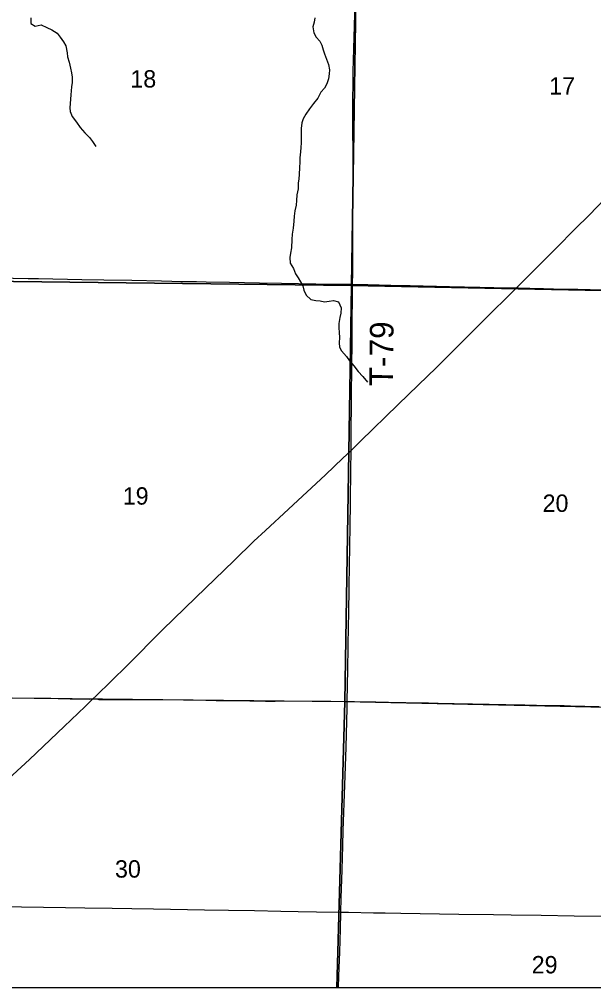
# Model space of a CAD drawing. Extents: x -8.5 to 18.7, y -20.3 to 7.
# Drawn here: x 11.753 to 14.521, y -20.262 to -15.596 of the extents above; entities that cross this region are included whole.
import ezdxf

# ---------------------------------------------------------------- set-up
doc = ezdxf.new("R2010")
doc.units = 0
for name, color, linetype in [('GM_X_Corporation', 7, 'Continuous'), ('GM_X_County_Road', 7, 'Continuous'), ('GM_X_Minor_River', 7, 'Continuous'), ('GM_X_Section', 7, 'Continuous'), ('GM_X_Section_Text', 7, 'Continuous'), ('GM_X_State_Route', 7, 'Continuous'), ('GM_X_Township_Road', 7, 'Continuous'), ('GM_X_Township_Road_Text', 7, 'Continuous'), ('GM_X_Unincorporated_Text', 7, 'Continuous'), ('SH_Cut_Line', 7, 'Continuous')]:
    doc.layers.add(name, color=color, linetype=linetype)

msp = doc.modelspace()

# ---------------------------------------------------------------- linework, layer by layer
at = {"layer": 'GM_X_Corporation'}
msp.add_lwpolyline([(11.351, -15.4961), (11.3472, -15.7708), (11.3457, -15.8603), (11.343, -16.0108), (11.3417, -16.0903), (11.339, -16.2358), (11.3374, -16.324), (11.3361, -16.4073), (11.3309, -16.7927), (11.331, -16.8266), (11.3313, -16.8312), (11.3321, -16.8414), (11.2969, -18.8581), (11.277, -19.7245), (11.2736, -19.8636), (11.2623, -20.262), (18.7413, -20.262)], dxfattribs=at)
at = {"layer": 'GM_X_County_Road'}
for points in [[(11.3326, -16.8425), (11.3671, -16.8392), (11.392, -16.8377), (11.4257, -16.8371), (11.4804, -16.8379), (11.5413, -16.8394), (11.6494, -16.841), (11.7961, -16.8438), (11.8446, -16.8445), (12.0534, -16.8489), (12.1603, -16.8513), (12.2958, -16.8534), (12.4375, -16.8563), (12.4873, -16.8575), (12.532, -16.8584), (12.6066, -16.8592), (12.6538, -16.8603), (12.7657, -16.8621), (12.9099, -16.8649), (13.0167, -16.8667), (13.1821, -16.8697), (13.2828, -16.8711), (13.3593, -16.8726)], [(13.3593, -16.8726), (13.4332, -16.8741), (13.5438, -16.8772), (13.637, -16.8789), (13.826, -16.8829), (13.9726, -16.8863), (14.0398, -16.8873), (14.1218, -16.8891), (14.1487, -16.8895)], [(14.1487, -16.8895), (14.1591, -16.8897), (14.2125, -16.8915), (14.2784, -16.893), (14.3268, -16.8937), (14.4449, -16.8962), (14.5643, -16.8985), (14.6686, -16.9014), (14.8228, -16.9045), (14.9657, -16.9071), (15.2454, -16.9126), (15.3212, -16.9133), (15.3705, -16.9142)], [(13.3333, -18.8824), (13.3362, -18.7269), (13.3397, -18.5155), (13.3406, -18.4646), (13.3433, -18.3266), (13.3467, -18.0382), (13.3487, -17.9276), (13.3513, -17.7572), (13.3517, -17.686), (13.3521, -17.673)], [(13.3025, -19.8984), (13.3043, -19.8304), (13.3084, -19.695), (13.3115, -19.5769), (13.314, -19.5049), (13.3213, -19.2862), (13.3274, -19.1035), (13.3327, -18.9146), (13.3333, -18.8824)], [(11.2741, -19.8647), (11.3221, -19.8657), (11.3817, -19.8672), (11.4936, -19.8684), (11.6552, -19.8712), (11.9747, -19.8761), (12.0692, -19.8767), (12.1997, -19.8796), (12.2954, -19.8809), (12.3998, -19.8829), (12.646, -19.8869), (12.7603, -19.8886), (12.8871, -19.8909), (13.0139, -19.8932), (13.0972, -19.8946), (13.1854, -19.8963), (13.3025, -19.8984)], [(13.2916, -20.262), (13.2932, -20.207), (13.2968, -20.0889), (13.3002, -19.9796), (13.3025, -19.8984)], [(13.3025, -19.8984), (13.3396, -19.8991), (13.4602, -19.9008), (13.5161, -19.9015), (13.5919, -19.9033), (13.8717, -19.9075), (14.0382, -19.9103), (14.124, -19.9116), (14.267, -19.9132), (14.4261, -19.9156), (14.6524, -19.9183), (14.7978, -19.9203), (14.8047, -19.9204)]]:
    msp.add_lwpolyline(points, dxfattribs=at)
at = {"layer": 'GM_X_Minor_River'}
for points in [[(11.8087, -15.5882), (11.8078, -15.6162), (11.8297, -15.6285), (11.8585, -15.6218), (11.885, -15.6348), (11.91, -15.6456), (11.9356, -15.6624), (11.95, -15.6814), (11.9665, -15.7042), (11.9771, -15.724), (11.9838, -15.7567), (11.9844, -15.7764), (11.9934, -15.8022), (11.9994, -15.8311), (12.0046, -15.8531), (12.0083, -15.8744), (12.0074, -15.9002), (12.0051, -15.9206), (12.0027, -15.9404), (12.0011, -15.9593), (11.9996, -15.9798), (11.9972, -16.0018), (11.9964, -16.0215), (11.9978, -16.0405), (12.0083, -16.064), (12.0279, -16.0907), (12.0467, -16.1173), (12.0686, -16.1432)], [(13.1767, -15.5877), (13.1736, -15.6089), (13.1667, -15.6324), (13.1727, -15.6605), (13.1832, -15.6811), (13.2005, -15.7016), (13.2103, -15.7206), (13.2178, -15.7419), (13.223, -15.7617), (13.2425, -15.8134), (13.247, -15.8384), (13.2469, -15.8581), (13.2423, -15.8824), (13.2353, -15.9059), (13.2231, -15.9271), (13.2056, -15.9467), (13.1919, -15.9755), (13.1713, -16.0012), (13.1515, -16.0276), (13.134, -16.0534), (13.1203, -16.0745), (13.1142, -16.095), (13.1118, -16.1215), (13.1115, -16.1906), (13.1091, -16.2126), (13.1083, -16.2338), (13.1052, -16.2634), (13.1043, -16.2846), (13.1027, -16.3104), (13.1011, -16.3438), (13.0995, -16.3635), (13.0971, -16.3847), (13.097, -16.412), (13.0908, -16.4416), (13.0884, -16.4689), (13.0876, -16.4909), (13.0814, -16.5189), (13.0768, -16.544), (13.0752, -16.5682), (13.072, -16.6023), (13.0681, -16.6312), (13.0657, -16.6569), (13.0641, -16.6964), (13.0594, -16.7222), (13.0563, -16.7426), (13.0577, -16.7699), (13.0743, -16.7966), (13.0833, -16.8217), (13.0961, -16.8414), (13.1186, -16.8795), (13.1246, -16.9), (13.1359, -16.9243), (13.1578, -16.9457), (13.1812, -16.9503), (13.2032, -16.9527), (13.2244, -16.9566), (13.2464, -16.9537), (13.2668, -16.9507), (13.2918, -16.9577), (13.3038, -16.9866), (13.303, -17.0116), (13.2976, -17.0328), (13.2929, -17.0616)], [(12.0686, -16.1432), (12.0912, -16.1646), (12.1056, -16.1836), (12.1214, -16.208)], [(13.2929, -17.0616), (13.2928, -17.0821), (13.295, -17.1056), (13.2964, -17.1292), (13.2948, -17.1549), (13.2963, -17.1747), (13.3053, -17.1937), (13.3302, -17.2211), (13.3445, -17.2409), (13.3656, -17.266), (13.3852, -17.2927), (13.4086, -17.3163), (13.4312, -17.3437)]]:
    msp.add_lwpolyline(points, dxfattribs=at)
at = {"layer": 'GM_X_Section'}
for points in [[(11.3525, -14.8396), (11.3525, -14.8313), (13.3845, -14.866), (13.3536, -16.8784), (11.3171, -16.8542)], [(13.3845, -14.866), (15.3877, -14.9113), (15.3636, -16.9183), (13.3536, -16.8784)], [(11.3171, -16.8542), (13.3536, -16.8784), (13.322, -18.8853), (11.2748, -18.8626)], [(13.3536, -16.8784), (15.3636, -16.9183), (15.3229, -18.9276), (13.322, -18.8853)]]:
    msp.add_lwpolyline(points, close=True, dxfattribs=at)
at = {"layer": 'GM_X_State_Route'}
for points in [[(14.1431, -16.8952), (14.1487, -16.8895), (14.1823, -16.8558), (14.2775, -16.7603), (14.3398, -16.6985), (14.4324, -16.6047), (14.4984, -16.5388), (14.6137, -16.4204)], [(13.3521, -17.673), (13.3978, -17.6285), (13.5781, -17.4525), (13.6758, -17.358), (13.7627, -17.2736), (13.8441, -17.1929), (13.9321, -17.1051), (14.0096, -17.0276), (14.1235, -16.9148), (14.1431, -16.8952)], [(11.2763, -19.7271), (11.2774, -19.7256), (11.3834, -19.5764), (11.4112, -19.537), (11.4283, -19.516), (11.4453, -19.498), (11.4687, -19.4748), (11.6608, -19.2934), (11.8019, -19.1622), (11.9683, -19.0034), (12.0706, -18.9071), (12.1075, -18.8708), (12.1214, -18.8577), (12.2722, -18.7091), (12.4429, -18.5376), (12.6032, -18.3814), (12.786, -18.2054), (12.8835, -18.1111), (12.9398, -18.0585), (13.0495, -17.9554), (13.2278, -17.7901), (13.3125, -17.7108), (13.3521, -17.673)]]:
    msp.add_lwpolyline(points, dxfattribs=at)
at = {"layer": 'GM_X_Township_Road'}
for points in [[(13.3593, -16.8726), (13.3597, -16.8163), (13.3604, -16.6758), (13.3609, -16.5117), (13.3611, -16.411), (13.3611, -16.2034), (13.3609, -16.1586), (13.3604, -16.0902), (13.3607, -16.0728), (13.3605, -16.002), (13.3613, -15.8851), (13.3622, -15.8466), (13.3653, -15.7372), (13.3705, -15.5707), (13.3715, -15.5148), (13.3731, -15.4539), (13.3784, -15.2836), (13.381, -15.1867), (13.3861, -15.004), (13.3883, -14.9443), (13.3898, -14.8834), (13.3905, -14.8568)], [(13.3521, -17.673), (13.3522, -17.6605), (13.3529, -17.6033), (13.3545, -17.4205), (13.3559, -17.2614), (13.3571, -17.1607), (13.3573, -17.0749), (13.359, -16.9133), (13.3593, -16.8726)], [(13.3333, -18.8824), (13.3362, -18.7269), (13.3397, -18.5155), (13.3406, -18.4646), (13.3433, -18.3266), (13.3467, -18.0382), (13.3487, -17.9276), (13.3513, -17.7572), (13.3517, -17.686), (13.3521, -17.673)], [(11.2973, -18.8592), (11.308, -18.8593), (11.4373, -18.8612), (11.5343, -18.8619), (11.6101, -18.8632), (11.8252, -18.8669), (11.8451, -18.8671), (11.8712, -18.8674), (11.9048, -18.8678), (11.9408, -18.8685), (11.9719, -18.8691), (11.998, -18.8696), (12.034, -18.8705), (12.0802, -18.8708), (12.0926, -18.8711), (12.1075, -18.8708)], [(12.1075, -18.8708), (12.119, -18.8707), (12.1272, -18.871), (12.1363, -18.8733), (12.1531, -18.8735), (12.1884, -18.8742), (12.2717, -18.8734), (12.3075, -18.8733)], [(12.3075, -18.8733), (12.3115, -18.8733), (12.3449, -18.8732), (12.4034, -18.8735), (12.5438, -18.8755), (12.652, -18.8769), (12.7017, -18.8778), (12.7316, -18.8785), (12.7713, -18.879), (12.8646, -18.8801), (12.9106, -18.8804), (12.9392, -18.8807), (12.9615, -18.881), (12.9864, -18.8812), (13.0224, -18.8806), (13.1641, -18.8815), (13.2548, -18.8822), (13.3206, -18.8825), (13.3333, -18.8824)], [(13.3025, -19.8984), (13.3043, -19.8304), (13.3084, -19.695), (13.3115, -19.5769), (13.314, -19.5049), (13.3213, -19.2862), (13.3274, -19.1035), (13.3327, -18.9146), (13.3333, -18.8824)], [(13.3333, -18.8824), (13.344, -18.8826), (13.3676, -18.8831), (13.4708, -18.8846), (13.5926, -18.8872), (13.615, -18.8877), (13.6721, -18.889), (13.7243, -18.8901), (13.7716, -18.8908), (13.8188, -18.892), (13.8486, -18.8932), (13.9367, -18.8946), (14.0983, -18.8968), (14.1891, -18.8998), (14.245, -18.9006), (14.3109, -18.9023), (14.378, -18.9029), (14.4402, -18.9048), (14.4775, -18.9059), (14.5471, -18.9071)], [(13.2916, -20.262), (13.2932, -20.207), (13.2968, -20.0889), (13.3002, -19.9796), (13.3025, -19.8984)]]:
    msp.add_lwpolyline(points, dxfattribs=at)
at = {"layer": 'GM_X_Unincorporated_Text'}
for points in [[(11.2465, -20.262), (13.2833, -20.262), (13.322, -18.8853), (11.2748, -18.8626)], [(13.2833, -20.262), (15.2847, -20.262), (15.3229, -18.9276), (13.322, -18.8853)]]:
    msp.add_lwpolyline(points, close=True, dxfattribs=at)
at = {"layer": 'SH_Cut_Line'}
msp.add_lwpolyline([(-8.4587, -10.6981), (-8.4587, -20.262), (18.7413, -20.262), (18.7413, -10.9039)], dxfattribs=at)

# ---------------------------------------------------------------- texts
at = {"layer": 'GM_X_Section_Text'}
for s, p in [('18', (12.2881, -15.9243)), ('17', (14.3065, -15.9582)), ('19', (12.2515, -17.9343)), ('20', (14.2748, -17.9693)), ('30', (12.214, -19.7318)), ('29', (14.2223, -20.1934))]:
    msp.add_text(s, height=0.08371, rotation=0, dxfattribs=at).set_placement(p)
at = {"layer": 'GM_X_Township_Road_Text'}
msp.add_text('T-79', height=0.11364, rotation=89.2955, dxfattribs=at).set_placement((13.5529, -17.3645))

doc.saveas('drawing.dxf')
